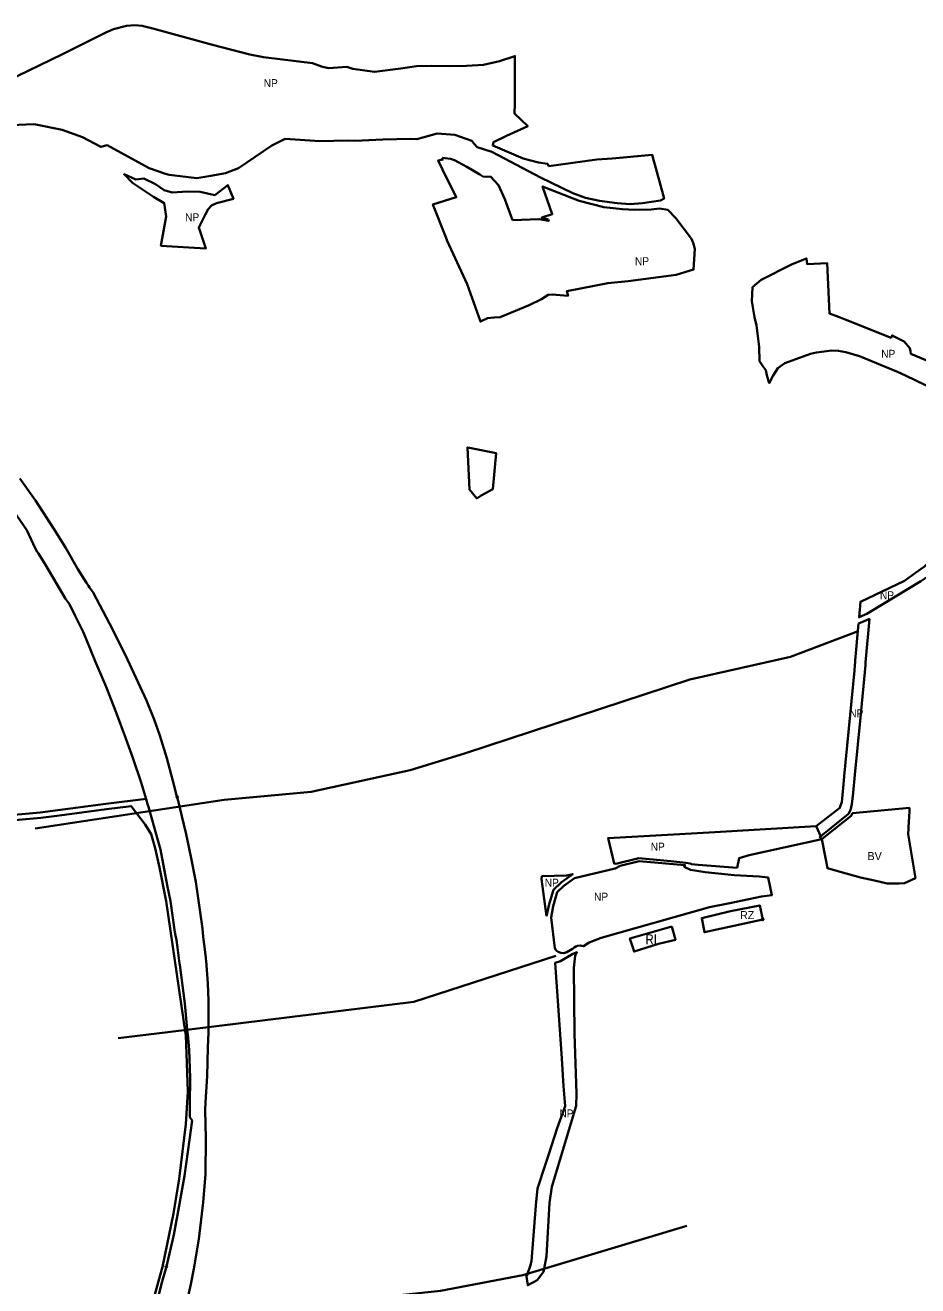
# Model space of a CAD drawing. Extents: x -650276 to -642489, y -1074311 to -1066720.
# Drawn here: x -645245 to -643906, y -1070703 to -1068813 of the extents above; entities that cross this region are included whole.
import ezdxf

# ---------------------------------------------------------------- set-up
doc = ezdxf.new("R2010")
doc.units = 0
doc.header["$LTSCALE"] = 4.8
doc.header["$PDMODE"] = 32
doc.header["$PDSIZE"] = 2.4
for name, color, linetype, lineweight in [('15', 7, 'Continuous', 35), ('24', 7, 'Continuous', 35), ('3', 7, 'Continuous', 35), ('48', 7, 'Continuous', 35), ('54', 7, 'Continuous', 35), ('6', 7, 'Continuous', 35), ('8', 7, 'Continuous', 35)]:
    doc.layers.add(name, color=color, linetype=linetype, lineweight=lineweight)
doc.layers.add('62', color=7, linetype='Continuous')

msp = doc.modelspace()

# ---------------------------------------------------------------- linework, layer by layer
at = {"layer": '15'}
for points in [[(-645061.76, -1069981.21), (-645064.052, -1069973.429), (-645124.233, -1069980.695), (-645222.809, -1069993.701), (-645350.784, -1070005.227)], [(-645350.591, -1070013.242), (-645221.99, -1070001.66), (-645194.003, -1069998.417), (-645123.206, -1069988.629), (-645086.484, -1069984.195), (-645065.235, -1070011.695)], [(-645033.53, -1070674.55), (-645022.64, -1070626.93), (-645014.07, -1070580.72), (-645006.44, -1070538.78), (-644998.92, -1070484.58), (-644995.14, -1070455.72), (-644998.17, -1070450.59), (-644998.25, -1070430.5), (-644997.87, -1070391.16), (-644999.47, -1070349.63), (-645001.64, -1070326.4), (-645001.81, -1070324.58), (-645002.308, -1070319.268), (-645005.98, -1070280.14), (-645013.51, -1070222.04), (-645013.77, -1070220.04), (-645016.92, -1070196.32), (-645018.56, -1070184.92), (-645021.14, -1070173.07), (-645027.49, -1070126.56), (-645032.21, -1070102.73), (-645042.27, -1070049.23), (-645047.28, -1070031.83), (-645054.73, -1070004.56), (-645060.612, -1069985.022), (-645061.76, -1069981.21)], [(-645065.235, -1070011.695), (-645056.555, -1070026.163), (-645050.293, -1070047.035), (-645043.92, -1070076.344), (-645034.122, -1070126.616), (-645004.791, -1070324.889), (-645004.523, -1070326.697)], [(-645004.523, -1070326.697), (-645004.434, -1070327.302), (-645001.312, -1070412.099), (-645004.327, -1070461.264), (-645014.277, -1070543.11), (-645023.048, -1070595.033), (-645039.574, -1070675.065)], [(-645039.574, -1070675.065), (-645045.493, -1070696.321), (-645059.308, -1070747.712), (-645059.403, -1070749.195), (-645053.21, -1070749.75), (-645052.4, -1070746.427), (-645046.63, -1070722.77), (-645041, -1070700.44), (-645033.53, -1070674.55)]]:
    msp.add_lwpolyline(points, dxfattribs=at)
msp.add_point((-645033.53, -1070674.55), dxfattribs=at)
at = {"layer": '24'}
for points in [[(-645322.13, -1069447.96), (-645309.62, -1069467.79), (-645303.57, -1069480.49), (-645268.57, -1069533.23), (-645242.75, -1069570.26), (-645230.42, -1069597.39), (-645227.27, -1069602.68), (-645225.7, -1069605.32), (-645214.76, -1069622.37), (-645198.41, -1069650.49), (-645185.17, -1069673.38), (-645179.12, -1069681.3), (-645170.3, -1069698.91), (-645158.43, -1069722.61), (-645153.44, -1069734.71), (-645140.27, -1069766.68), (-645123.84, -1069805.38), (-645108.74, -1069843.58), (-645094.42, -1069882.65), (-645083.31, -1069913.37), (-645071.53, -1069948.89), (-645063.96, -1069973.73), (-645063.23, -1069976.2), (-645062.57, -1069978.46)], [(-645017.46, -1069970.61), (-645018.28, -1069967.49), (-645024.45, -1069944.43), (-645032.85, -1069912.07), (-645043.5, -1069878.37), (-645051.78, -1069854.2), (-645063.26, -1069825.99), (-645095.1, -1069757.62), (-645118.98, -1069710.08), (-645143.56, -1069664.05), (-645148.8, -1069656.1), (-645150.3, -1069653.84), (-645153.33, -1069649.24), (-645166.67, -1069629), (-645184.88, -1069596.58), (-645202.56, -1069568.23), (-645230.1, -1069525.98), (-645253.4, -1069493.06)], [(-644996.88, -1070059.73), (-645004.02, -1070026.44), (-645010.54, -1069999.3), (-645015.548, -1069978.177), (-645016.01, -1069976.23), (-645016.89, -1069972.82), (-645017.46, -1069970.61)], [(-645062.57, -1069978.46), (-645061.76, -1069981.21), (-645060.612, -1069985.022), (-645054.73, -1070004.56), (-645047.28, -1070031.83), (-645042.27, -1070049.23), (-645032.21, -1070102.73), (-645027.49, -1070126.56), (-645021.14, -1070173.07), (-645018.56, -1070184.92), (-645016.92, -1070196.32), (-645013.77, -1070220.04), (-645013.51, -1070222.04), (-645005.98, -1070280.14), (-645002.308, -1070319.268), (-645001.81, -1070324.58), (-645001.64, -1070326.4), (-644999.47, -1070349.63), (-644997.87, -1070391.16), (-644998.25, -1070430.5), (-644998.17, -1070450.59), (-644995.14, -1070455.72), (-644998.92, -1070484.58), (-645006.44, -1070538.78), (-645014.07, -1070580.72), (-645022.64, -1070626.93), (-645033.53, -1070674.55)], [(-645001.71, -1070723.39), (-644997.14, -1070700.88), (-644992.6, -1070677.92), (-644985.04, -1070633.43), (-644978.44, -1070578.56), (-644975.05, -1070536.16), (-644974.44, -1070482.48), (-644975.29, -1070440.14), (-644974.69, -1070427.86), (-644972.48, -1070389.15), (-644971.37, -1070345.98), (-644970.61, -1070323.44), (-644970.55, -1070321.56), (-644970.524, -1070315.358), (-644970.36, -1070275.49), (-644971.47, -1070250.14), (-644974, -1070216.2), (-644974.29, -1070213.17), (-644974.49, -1070210.98), (-644976.94, -1070191.41), (-644978.49, -1070180.05), (-644979.57, -1070167.9), (-644984.21, -1070132.81), (-644989.62, -1070097.79), (-644996.88, -1070059.73)], [(-645033.53, -1070674.55), (-645041, -1070700.44), (-645046.63, -1070722.77)]]:
    msp.add_lwpolyline(points, dxfattribs=at)
for p in [(-645017.46, -1069970.61), (-645033.53, -1070674.55)]:
    msp.add_point(p, dxfattribs=at)
at = {"layer": '3'}
msp.add_lwpolyline([(-643920.84, -1070026.46), (-643920.29, -1070017.73), (-643920.16, -1070015.69), (-643918.69, -1069992.23), (-643918.88, -1069986.82), (-644004.06, -1069994.59), (-644005.92, -1069998.62), (-644044.7, -1070029.04), (-644050.12, -1070033.64), (-644044.18, -1070064.43), (-644041.71, -1070077.29), (-644022.77, -1070082.66), (-643991.99, -1070091.37), (-643971.03, -1070095.79), (-643951.99, -1070100.35), (-643933.96, -1070100.18), (-643926.33, -1070099.5), (-643909.87, -1070091.95)], close=True, dxfattribs=at)
at = {"layer": '48'}
msp.add_line((-644015.12, -1069254.24), (-644024.93, -1069250.23), dxfattribs=at)
for points in [[(-645122.25, -1068993.21), (-645059.3, -1069027.45), (-645034.792, -1069035.879), (-645029.47, -1069037.71), (-644988.11, -1069042.51), (-644966.91, -1069038.845), (-644944.9, -1069035.04), (-644925.35, -1069027.75), (-644875.57, -1068993.47), (-644855.56, -1068983.38), (-644803.31, -1068986.97), (-644761.88, -1068986.27), (-644750.67, -1068986.34), (-644708.6, -1068984.54), (-644667.57, -1068983.47), (-644657.61, -1068983.91), (-644627.41, -1068975.6), (-644600.67, -1068977.77), (-644575.29, -1068986.48), (-644572.05, -1068991.08), (-644567.09, -1068996.26), (-644545.54, -1069003.12), (-644472.37, -1069041.44), (-644424.01, -1069065.01), (-644404.96, -1069071.76), (-644383.55, -1069076.57), (-644357.4, -1069079.84), (-644337.6, -1069081.29), (-644319.2, -1069079.82), (-644292.27, -1069076.05), (-644286.94, -1069073.19), (-644304.6, -1069007.55), (-644364.53, -1069012.83), (-644387.91, -1069014.64), (-644459.67, -1069024.41), (-644461.74, -1069020.83), (-644475.09, -1069018.99), (-644498.28, -1069013.19), (-644544.02, -1068993.75), (-644543.05, -1068988.64), (-644523.4, -1068978.98), (-644491.31, -1068964.35), (-644511.47, -1068945.37), (-644510.75, -1068931.16), (-644510.567, -1068897.909), (-644510.62, -1068859.35), (-644533.84, -1068867.2), (-644557.75, -1068872.33), (-644583.26, -1068874.26), (-644608.71, -1068874.78), (-644636.55, -1068874.02), (-644658.39, -1068874.59), (-644681.99, -1068878.15), (-644721.29, -1068883.2), (-644753.71, -1068878.41), (-644763.04, -1068875.63), (-644790.41, -1068877.73), (-644800.87, -1068874.97), (-644814.47, -1068870.12), (-644834.84, -1068867.4), (-644887.91, -1068860.82), (-644908.26, -1068856.91), (-644964.45, -1068842.38), (-645053.97, -1068818.31), (-645070.05, -1068814), (-645081.12, -1068813.15), (-645093.56, -1068814.27), (-645112.77, -1068819.13), (-645124.36, -1068824.11), (-645190.22, -1068857.23), (-645239.85, -1068880.94)], [(-645239.85, -1068880.94), (-645257.5, -1068889.68), (-645324.79, -1068914.82), (-645335.45, -1068915.77), (-645346.96, -1068932.01), (-645365.23, -1068962.32), (-645377.9, -1068997.99), (-645392.3, -1069024.38), (-645383.62, -1069017.57), (-645396.53, -1069030.88), (-645371.35, -1069010.64), (-645350.17, -1068993.33), (-645328.55, -1068980.37), (-645311.99, -1068972.74), (-645292.77, -1068966.91), (-645275.45, -1068964.38), (-645255.21, -1068962.49), (-645232.4, -1068961.67), (-645229.27, -1068962.28), (-645189.84, -1068969.91), (-645159.37, -1068981.11), (-645131.73, -1068995.69), (-645122.25, -1068993.21)], [(-644619.1, -1069011.81), (-644618.8, -1069014.7), (-644625.69, -1069015.84)], [(-644583.05, -1069025.29), (-644601.43, -1069015.74), (-644607.16, -1069013.56), (-644619.1, -1069011.81)], [(-644625.69, -1069015.84), (-644619.54, -1069029.55), (-644598.81, -1069071.02)], [(-644553.62, -1069040.53), (-644558.56, -1069039.86), (-644563.19, -1069037.21), (-644583.05, -1069025.29)], [(-644535.13, -1069053.18), (-644547.31, -1069040.11), (-644553.62, -1069040.53)], [(-644514.47, -1069105.62), (-644525.83, -1069073.84), (-644535.13, -1069053.18)], [(-644281.26, -1069090.19), (-644293.62, -1069088.17), (-644306.29, -1069089.37), (-644331.44, -1069090), (-644349.32, -1069089.22), (-644377.36, -1069085.89), (-644414.04, -1069076.75), (-644469.28, -1069054.8), (-644454.75, -1069096.51)], [(-644598.81, -1069071.02), (-644633.66, -1069082), (-644614.41, -1069131.08), (-644612.3, -1069136.45), (-644582.29, -1069201.27), (-644562.47, -1069257.56), (-644552.01, -1069252.24), (-644541.83, -1069251.66), (-644532.71, -1069251.12), (-644489.27, -1069233.04), (-644470.64, -1069224), (-644460.97, -1069217.61)], [(-644454.75, -1069096.51), (-644470.37, -1069101.55), (-644461.01, -1069104.36), (-644459.82, -1069106.73), (-644474.33, -1069104.22), (-644514.47, -1069105.62)], [(-644242.48, -1069179.49), (-644240.67, -1069148.58), (-644243.14, -1069139.47), (-644245.65, -1069133.66), (-644269.11, -1069102.31), (-644281.26, -1069090.19)], [(-644024.93, -1069250.23), (-644038.83, -1069245.65), (-644042.37, -1069169.77), (-644071.97, -1069171.72), (-644073.35, -1069162.84), (-644094.79, -1069171.27)], [(-644460.97, -1069217.61), (-644454.87, -1069217.05), (-644430.91, -1069218.82), (-644432.53, -1069212.02), (-644371.08, -1069199.84), (-644340.83, -1069197.13), (-644268.7, -1069187.42), (-644242.48, -1069179.49)], [(-644094.79, -1069171.27), (-644141.24, -1069195.17), (-644154.36, -1069206.06), (-644155.37, -1069226.72), (-644151.11, -1069250.7), (-644148.22, -1069263.22), (-644144.05, -1069295.67)], [(-643732.705, -1069454.79), (-643726.74, -1069450.72), (-643777.27, -1069389.71), (-643791.02, -1069364.54), (-643798.1, -1069353.51), (-643804.83, -1069348.99), (-643817.06, -1069348.14), (-643826.21, -1069352.92), (-643838.69, -1069360.79), (-643853.56, -1069364.44), (-643856.43, -1069362.68), (-643885.63, -1069318.72), (-643916.78, -1069305.89), (-643917.36, -1069302.04), (-643918.08, -1069297.33), (-643926.74, -1069287.37), (-643944.89, -1069278.32), (-643946.16, -1069281.84), (-644015.12, -1069254.24)], [(-644144.05, -1069295.67), (-644143.54, -1069317.05), (-644138.55, -1069324.23), (-644134.15, -1069330.45), (-644132.52, -1069338.02), (-644129.09, -1069349.83), (-644123.21, -1069338.41), (-644116.33, -1069327.36), (-644105.5, -1069320.03), (-644067.08, -1069306.15), (-644058.05, -1069304.02), (-644054.35, -1069303.55)], [(-644054.35, -1069303.55), (-644035.89, -1069301.02), (-644025.24, -1069301.38), (-644014.19, -1069303.36), (-643993.91, -1069309.57), (-643936.87, -1069332.93), (-643924.42, -1069338.29), (-643894.84, -1069352.76), (-643885.22, -1069355.58), (-643879.48, -1069359.13), (-643876.34, -1069360.61), (-643856.58, -1069377.59), (-643844.28, -1069382.26), (-643823.72, -1069382.61), (-643815.93, -1069384.23), (-643801.36, -1069387.23), (-643788.63, -1069393.7), (-643776.78, -1069401.87), (-643732.705, -1069454.79)], [(-644058.55, -1070014.4), (-644219.33, -1070023.53), (-644370.87, -1070032.13), (-644361.74, -1070070.32), (-644359.02, -1070070.67), (-644324.72, -1070062.44), (-644276.85, -1070066.62), (-644254.13, -1070069.08)], [(-644177.01, -1070076.69), (-644177.01, -1070076.69), (-644174.12, -1070062.16), (-644159.02, -1070057.84), (-644050.12, -1070033.64), (-644053.18, -1070030.57), (-644051.913, -1070029.549), (-644058.55, -1070014.4)], [(-644254.13, -1070069.08), (-644254.25, -1070069.37), (-644247.72, -1070070.21), (-644245.9, -1070071.26), (-644235.49, -1070072.08), (-644177.01, -1070076.69)]]:
    msp.add_lwpolyline(points, dxfattribs=at)
for points in [[(-644514.47, -1069105.62), (-644474.33, -1069104.22), (-644459.82, -1069106.73), (-644461.01, -1069104.36), (-644470.37, -1069101.55), (-644454.75, -1069096.51), (-644469.28, -1069054.8), (-644414.04, -1069076.75), (-644377.36, -1069085.89), (-644349.32, -1069089.22), (-644331.44, -1069090), (-644306.29, -1069089.37), (-644293.62, -1069088.17), (-644281.26, -1069090.19), (-644269.11, -1069102.31), (-644245.65, -1069133.66), (-644243.14, -1069139.47), (-644240.67, -1069148.58), (-644242.48, -1069179.49), (-644268.7, -1069187.42), (-644340.83, -1069197.13), (-644371.08, -1069199.84), (-644432.53, -1069212.02), (-644430.91, -1069218.82), (-644454.87, -1069217.05), (-644460.97, -1069217.61), (-644470.64, -1069224), (-644489.27, -1069233.04), (-644532.71, -1069251.12), (-644541.83, -1069251.66), (-644552.01, -1069252.24), (-644562.47, -1069257.56), (-644582.29, -1069201.27), (-644612.3, -1069136.45), (-644614.41, -1069131.08), (-644633.66, -1069082), (-644598.81, -1069071.02), (-644619.54, -1069029.55), (-644625.69, -1069015.84), (-644618.8, -1069014.7), (-644619.1, -1069011.81), (-644607.16, -1069013.56), (-644601.43, -1069015.74), (-644583.05, -1069025.29), (-644563.19, -1069037.21), (-644558.56, -1069039.86), (-644553.62, -1069040.53), (-644547.31, -1069040.11), (-644535.13, -1069053.18), (-644525.83, -1069073.84)], [(-645067.65, -1069043.18), (-645049.91, -1069051.48), (-645036.97, -1069060.39), (-645024.75, -1069063.81), (-645001.82, -1069062.43), (-644982.96, -1069062.92), (-644961.05, -1069067.78), (-644941.27, -1069052.9), (-644932.95, -1069073.65), (-644958.25, -1069079.99), (-644965.95, -1069083.67), (-644970.84, -1069088.8), (-644975.56, -1069097.564), (-644985.15, -1069116.67), (-644974.34, -1069147.85), (-645041.751, -1069143.816), (-645034.13, -1069099.79), (-645036.87, -1069079.78), (-645052.83, -1069070.4), (-645075.206, -1069055.523), (-645084.19, -1069049.55), (-645096.97, -1069036.63), (-645079.65, -1069044.32)], [(-644578.92, -1069446.8), (-644539, -1069454.88), (-644543.99, -1069508.88), (-644561.24, -1069518.27), (-644567.976, -1069522.752), (-644579.047, -1069509.608), (-644581.87, -1069446.28)], [(-644578.92, -1069446.8), (-644581.87, -1069446.28), (-644579.047, -1069509.608), (-644567.976, -1069522.752), (-644561.24, -1069518.27), (-644543.99, -1069508.88), (-644539, -1069454.88)], [(-643870.697, -1069601.241), (-643895.951, -1069625.069), (-643909.616, -1069634.267), (-643926.229, -1069646.367), (-643992.34, -1069677.76), (-643994.36, -1069701.05), (-643982.84, -1069695.93), (-643977.582, -1069692.76), (-643901.55, -1069646.92), (-643886.62, -1069636.87), (-643873.82, -1069625.05), (-643872.55, -1069620.75), (-643870.44, -1069613.56), (-643863.92, -1069613.9)], [(-643995.17, -1069710.42), (-643999.94, -1069765.62), (-644000.79, -1069775.42), (-644001.04, -1069778.063), (-644001.29, -1069780.7), (-644016.47, -1069938.99), (-644017.15, -1069945.93), (-644020.26, -1069978.38), (-644022.43, -1069984.87), (-644022.99, -1069986.58), (-644058.55, -1070014.4), (-644051.913, -1070029.549), (-644049.311, -1070027.453), (-644009.95, -1069995.74), (-644006.96, -1069990.34), (-644005.06, -1069981.28), (-644003.06, -1069964.06), (-644000.52, -1069937.19), (-643992.27, -1069851.31), (-643984.845, -1069772.863), (-643984.44, -1069768.58), (-643978.85, -1069703.4), (-643986.744, -1069706.796)], [(-644381.21, -1070181.71), (-644218.65, -1070135.75), (-644188.44, -1070129.43), (-644140.72, -1070119.57), (-644125, -1070117.83), (-644130.91, -1070091.1), (-644144.13, -1070089.47), (-644181.81, -1070087.51), (-644191.26, -1070086.47), (-644225.13, -1070082.95), (-644247.3, -1070079.69), (-644256.54, -1070075.02), (-644255.52, -1070072.5), (-644324.42, -1070066.48), (-644352.71, -1070073.46), (-644360.41, -1070077.91), (-644421.26, -1070091.99), (-644437.34, -1070103.76), (-644447.13, -1070113.11), (-644453.22, -1070133.99), (-644456.41, -1070151.18), (-644450.72, -1070196.97), (-644448.76, -1070200.77), (-644445.9, -1070202.83), (-644441.8, -1070204.26), (-644437.415, -1070204.436), (-644432.53, -1070203.32), (-644424.14, -1070198.29), (-644421.88, -1070196.28), (-644419.51, -1070194.76), (-644416.67, -1070193.7), (-644412.54, -1070193.18), (-644407.55, -1070194.16), (-644399.15, -1070188.55)], [(-644463.28, -1070149.42), (-644459.09, -1070131.08), (-644452.65, -1070109.46), (-644440.64, -1070098.4), (-644423.99, -1070086.17), (-644433.19, -1070088.37), (-644470.17, -1070089.43), (-644470.55, -1070093.61)], [(-644491.691, -1070685.524), (-644491.82, -1070685.92), (-644493.5, -1070689.75), (-644491.42, -1070702.64), (-644477.46, -1070695.09), (-644467.84, -1070682.37), (-644466.998, -1070678.065), (-644463.28, -1070659.06), (-644458.85, -1070579.04), (-644455.2, -1070554.88), (-644418.69, -1070433.36), (-644418.23, -1070415.62), (-644421.45, -1070325.29), (-644422.5, -1070226.42), (-644420.14, -1070208.56), (-644418.61, -1070204.51), (-644417.36, -1070203.24), (-644421.47, -1070204.77), (-644423.66, -1070205.86), (-644442.2, -1070216.72), (-644450.15, -1070219.06), (-644445.28, -1070290.84), (-644440.36, -1070362.62), (-644437.53, -1070404.1), (-644435.51, -1070433.85), (-644447.14, -1070467.28), (-644460.5, -1070507.68), (-644464.98, -1070521.13), (-644476.94, -1070557.45), (-644479.06, -1070583.13), (-644485.64, -1070666.7), (-644488.01, -1070674.2)]]:
    msp.add_lwpolyline(points, close=True, dxfattribs=at)
at = {"layer": '54'}
for points in [[(-645230.538, -1070017.864), (-644946.741, -1069974.541), (-644816.387, -1069962.572), (-644667.646, -1069930.034), (-644586.303, -1069905.244), (-644248.286, -1069794.155), (-644097.378, -1069760.147), (-643995.653, -1069721.915)], [(-645105.781, -1070331.996), (-645031.648, -1070322.877), (-644662.188, -1070277.428), (-644449.34, -1070208.499)], [(-645155.795, -1070741.501), (-645051.039, -1070746.492), (-644927.167, -1070743.394), (-644622.134, -1070710.86), (-644498.737, -1070687.652), (-644252.543, -1070613.291)]]:
    msp.add_lwpolyline(points, dxfattribs=at)
at = {"layer": '6'}
msp.add_lwpolyline([(-644275.05, -1070164.59), (-644338.06, -1070182.64), (-644331.9, -1070202.4), (-644295.01, -1070190.9), (-644269.84, -1070184.57)], close=True, dxfattribs=at)
at = {"layer": '8'}
for p, q in [((-644138.78, -1070154.07), (-644143.31, -1070132.95)), ((-644182.31, -1070163.66), (-644138.78, -1070154.07))]:
    msp.add_line(p, q, dxfattribs=at)
msp.add_lwpolyline([(-644143.31, -1070132.95), (-644143.31, -1070132.95), (-644143.31, -1070132.95), (-644187.11, -1070141.58), (-644230.4, -1070152.08), (-644226.23, -1070173.28), (-644182.31, -1070163.66)], dxfattribs=at)
msp.add_point((-644138.78, -1070154.07), dxfattribs=at)

# ---------------------------------------------------------------- texts
at = {"layer": '62'}
for s, height, width, p in [('NP', 12, 0.95, (-644887.583, -1068906.041)), ('NP', 12, 0.95, (-645005.583, -1069107.041)), ('NP', 12, 0.95, (-644330.583, -1069173.041)), ('NP', 12, 0.95, (-643961.069, -1069311.925)), ('NP', 12, 0.95, (-643962.985, -1069673.967)), ('NP', 12, 0.95, (-644008.985, -1069850.967)), ('NP', 12, 0.95, (-644306.985, -1070050.967)), ('NP', 12, 0.95, (-644465.985, -1070104.967)), ('NP', 12, 0.95, (-644391.985, -1070125.967)), ('RI', 15, 0.85, (-644314.705, -1070191.481)), ('NP', 12, 0.95, (-644444, -1070450.967))]:
    msp.add_text(s, height=height, dxfattribs=dict(at, width=width)).set_placement(p)
for s, p in [('BV', (-643981.639, -1070065.037)), ('RZ', (-644172.882, -1070153.612))]:
    msp.add_text(s, height=12, dxfattribs=at).set_placement(p)

doc.saveas('drawing.dxf')
